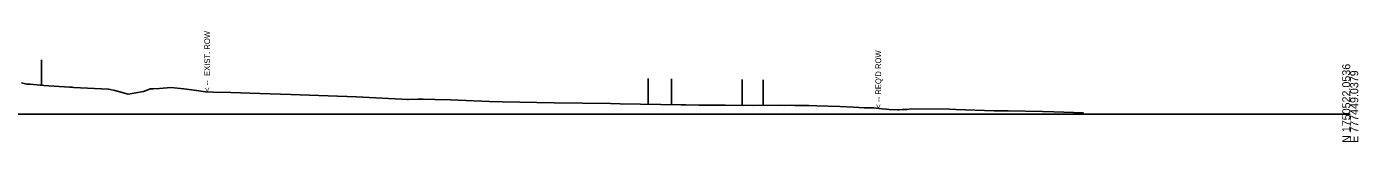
# Model space of a CAD drawing. Extents: x 776426 to 854588, y 1736205 to 1756790.
# Drawn here: x 805207.6 to 805673.6, y 1751205.1 to 1751243.9 of the extents above; entities that cross this region are included whole.
import ezdxf

# ---------------------------------------------------------------- set-up
doc = ezdxf.new("R2010")
doc.units = 0
for name, color, linetype in [('63', 7, 'Continuous'), ('DTM CONTOURS_MAJOR_TX', 7, 'Continuous'), ('DTM_X_FLOW_ARROWS', 7, 'Continuous'), ('TRANS_EOP_PAVED', 7, 'Continuous'), ('TRANS_UNPAVED_SHOULDERS', 7, 'Continuous'), ('XS_P_ROW', 7, 'Continuous'), ('XS_X_ROW', 7, 'Continuous')]:
    doc.layers.add(name, color=color, linetype=linetype)

msp = doc.modelspace()

# ---------------------------------------------------------------- linework, layer by layer
at = {"layer": '63'}
msp.add_line((805212.79, 1751233.88), (805212.79, 1751224.88), dxfattribs=at)
msp.add_line((805212.79, 1751233.88), (805212.79, 1751224.88), dxfattribs=at)
at = {"layer": 'DTM CONTOURS_MAJOR_TX'}
msp.add_line((805170.79, 1751214.76), (805670.79, 1751214.76), dxfattribs=at)
at = {"layer": 'DTM_X_FLOW_ARROWS'}
msp.add_lwpolyline([(805205.87, 1751225.78), (805207.72, 1751225.37), (805208.82, 1751225.27), (805213.59, 1751224.8), (805222.64, 1751224.27), (805223.54, 1751224.21), (805223.97, 1751224.2), (805236.32, 1751223.62), (805238.54, 1751223.08), (805243.11, 1751221.79), (805248.51, 1751222.72), (805250.94, 1751223.64), (805251.86, 1751223.68), (805254.15, 1751223.8), (805258.1, 1751224.14), (805262.58, 1751223.71), (805266.24, 1751223.2), (805270.16, 1751222.64), (805272.92, 1751222.57), (805279.07, 1751222.36), (805289.27, 1751222.06), (805300.02, 1751221.65), (805313.12, 1751221.2), (805323.07, 1751220.85), (805334.25, 1751220.27), (805338.92, 1751220.05), (805340.88, 1751220), (805341.21, 1751220), (805344.5, 1751220.02), (805346.38, 1751220.01), (805350.51, 1751219.94), (805355.99, 1751219.83), (805369.6, 1751219.3), (805374.1, 1751219.19), (805392.23, 1751218.81), (805411.98, 1751218.52), (805415.28, 1751218.48), (805436.7, 1751218.06), (805438.33, 1751218.03), (805442.8, 1751218.01), (805451.62, 1751218.01), (805452.03, 1751218.02), (805461.51, 1751217.83), (805470.72, 1751217.92), (805472.84, 1751217.9), (805474.76, 1751217.91), (805476.38, 1751217.89), (805480.35, 1751217.81), (805481.35, 1751217.79), (805484.14, 1751217.76), (805492.21, 1751217.48), (805496.97, 1751217.27), (805500.66, 1751217.04), (805504.12, 1751217), (805505.9, 1751216.77), (805507.01, 1751216.67), (805508.54, 1751216.55), (805509.42, 1751216.5), (805512.34, 1751216.33), (805512.88, 1751216.33), (805514.03, 1751216.39), (805515.59, 1751216.41), (805517.13, 1751216.68), (805530.59, 1751216.51), (805532.81, 1751216.48), (805546.2, 1751216.03), (805548.05, 1751215.98), (805551.07, 1751215.95), (805563.05, 1751215.72), (805567.09, 1751215.62), (805577.43, 1751215.29)], dxfattribs=at)
at = {"layer": 'TRANS_EOP_PAVED'}
for p, q in [((805433.22, 1751227.13), (805433.22, 1751218.13)), ((805433.22, 1751227.13), (805433.22, 1751218.13)), ((805457.95, 1751226.9), (805457.95, 1751217.9)), ((805457.95, 1751226.9), (805457.95, 1751217.9))]:
    msp.add_line(p, q, dxfattribs=at)
at = {"layer": 'TRANS_UNPAVED_SHOULDERS'}
for p, q in [((805425.17, 1751227.29), (805425.17, 1751218.29)), ((805425.17, 1751227.29), (805425.17, 1751218.29)), ((805465.4, 1751226.87), (805465.4, 1751217.87)), ((805465.4, 1751226.87), (805465.4, 1751217.87))]:
    msp.add_line(p, q, dxfattribs=at)

# ---------------------------------------------------------------- texts
at = {"layer": 'DTM CONTOURS_MAJOR_TX'}
for s, p in [('N 1750522.0536', (805670.79, 1751204.76)), ('E 777449.0379', (805673.59, 1751204.76))]:
    msp.add_text(s, height=2.8, rotation=90, dxfattribs=at).set_placement(p)
at = {"layer": 'XS_P_ROW'}
msp.add_text("< -- REQ'D ROW", height=2, rotation=90, dxfattribs=at).set_placement((805506.64, 1751216.81))
at = {"layer": 'XS_X_ROW'}
msp.add_text('< --  EXIST. ROW', height=2, rotation=90, dxfattribs=at).set_placement((805271.79, 1751222.62))

doc.saveas('drawing.dxf')
